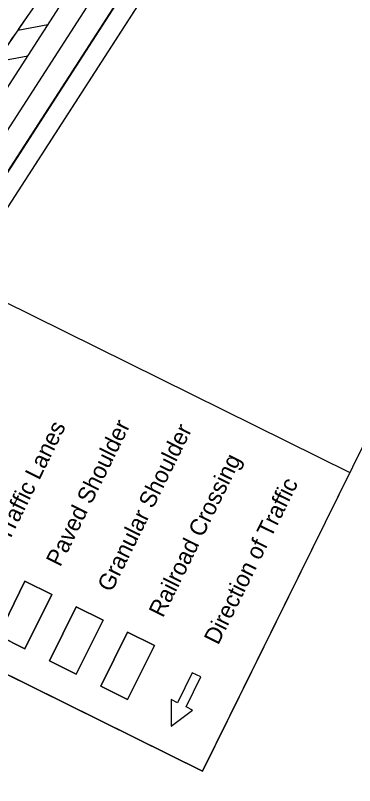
# Model space of a CAD drawing. Extents: x 14090526 to 14125274, y 8637242 to 8677144.
# Drawn here: x 14119217.3 to 14119395, y 8668599.6 to 8669002.7 of the extents above; entities that cross this region are included whole.
import ezdxf

# ---------------------------------------------------------------- set-up
doc = ezdxf.new("R2010")
doc.units = 0
for name, color, linetype in [('dsn_stg_shd_prev', 7, 'Continuous'), ('dsnNonPlotable', 7, 'Continuous'), ('dsnPaintExistingBrokenLaneLineWhite', 7, 'Continuous'), ('dsnPaintExistingChannelizingLaneYellow', 7, 'Continuous'), ('dsnPaintExistingEdgeLineRightWhite', 7, 'Continuous'), ('dsnShadingPaved', 7, 'Continuous'), ('dsnStgShadingPropPav', 7, 'Continuous'), ('dsnTextOverlapOdd', 7, 'Continuous')]:
    doc.layers.add(name, color=color, linetype=linetype)

msp = doc.modelspace()

# ---------------------------------------------------------------- linework, layer by layer
at = {"layer": 'dsn_stg_shd_prev'}
msp.add_lwpolyline([(14119498.98, 8669345.14), (14119201.18, 8668883.8), (14119172.86, 8668902.61), (14119172.76, 8668902.45), (14119141.1, 8668923.47)], dxfattribs=at)
at = {"layer": 'dsnNonPlotable'}
msp.add_lwpolyline([(14119315.27, 8668607.09), (14120010, 8670012.23), (14119557.31, 8670236.05), (14118862.58, 8668830.91)], close=True, dxfattribs=at)
at = {"layer": 'dsnPaintExistingBrokenLaneLineWhite'}
msp.add_line((14119527.44, 8669429.79), (14119185.09, 8668899.43), dxfattribs=at)
at = {"layer": 'dsnPaintExistingChannelizingLaneYellow'}
for p, q in [((14119175.01, 8668905.94), (14119397.41, 8669250.48)), ((14119334.31, 8669161.88), (14119223.77, 8669002.54)), ((14119218.51, 8668994.94), (14119234.32, 8668997.83)), ((14119207.17, 8668978.47), (14119223.83, 8668981.58))]:
    msp.add_line(p, q, dxfattribs=at)
msp.add_arc((14123732.96, 8665874.38), 5488, 145.2497, 146.41498, dxfattribs=at)
at = {"layer": 'dsnPaintExistingEdgeLineRightWhite'}
msp.add_line((14119195.17, 8668892.92), (14119537.53, 8669423.29), dxfattribs=at)
at = {"layer": 'dsnShadingPaved'}
for p, q in [((14119175.01, 8668905.94), (14119517.35, 8669436.29)), ((14119334.31, 8669161.88), (14119223.77, 8669002.54))]:
    msp.add_line(p, q, dxfattribs=at)
msp.add_lwpolyline([(14119537.53, 8669423.29), (14119537.53, 8669423.29), (14119195.17, 8668892.92)], dxfattribs=at)
msp.add_arc((14123732.96, 8665874.38), 5488, 145.2497, 157.1633, dxfattribs=at)
at = {"layer": 'dsnStgShadingPropPav'}
msp.add_lwpolyline([(14119420.33, 8669223.29), (14119201.18, 8668883.8), (14119172.86, 8668902.61), (14119172.76, 8668902.45), (14119141.1, 8668923.47)], dxfattribs=at)
at = {"layer": 'dsnTextOverlapOdd'}
for points in [[(14119132.8, 8668697.31), (14119210.08, 8668853.62), (14119392.55, 8668763.4), (14119315.27, 8668607.09)], [(14119132.8, 8668697.31), (14119210.08, 8668853.62), (14119392.55, 8668763.4), (14119315.27, 8668607.09)], [(14119208.22, 8668678.15), (14119222.23, 8668706.49), (14119236.3, 8668699.53), (14119222.29, 8668671.19)], [(14119236.3, 8668699.53), (14119222.23, 8668706.49), (14119208.22, 8668678.15), (14119222.29, 8668671.19)], [(14119235.11, 8668664.86), (14119249.12, 8668693.19), (14119263.19, 8668686.23), (14119249.19, 8668657.9)], [(14119263.19, 8668686.23), (14119249.12, 8668693.19), (14119235.11, 8668664.86), (14119249.19, 8668657.9)], [(14119262, 8668651.56), (14119276.01, 8668679.89), (14119290.09, 8668672.93), (14119276.08, 8668644.6)], [(14119290.09, 8668672.93), (14119276.01, 8668679.89), (14119262, 8668651.56), (14119276.08, 8668644.6)]]:
    msp.add_lwpolyline(points, close=True, dxfattribs=at)
msp.add_lwpolyline([(14119302.18, 8668642.98), (14119298.82, 8668644.64), (14119298.88, 8668630.66), (14119310.02, 8668639.1), (14119306.66, 8668640.76), (14119314.42, 8668656.45), (14119309.94, 8668658.66), (14119302.18, 8668642.98)], dxfattribs=at)

# ---------------------------------------------------------------- texts
for s, p in [('Paved Shoulder', (14119240.77, 8668713.67)), ('Traffic Lanes', (14119213.88, 8668726.97)), ('Granular Shoulder', (14119267.66, 8668700.37)), ('Railroad Crossing', (14119294.56, 8668687.08)), ('Direction of Traffic', (14119323.51, 8668672.76))]:
    msp.add_text(s, height=8.75, rotation=63.6912, dxfattribs=at).set_placement(p)

doc.saveas('drawing.dxf')
